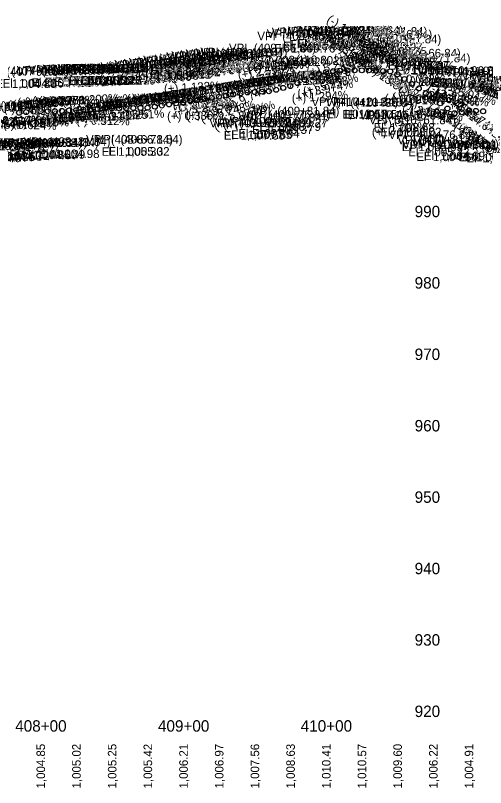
# Model space of a CAD drawing. Extents: x 16972137 to 16976737, y 12558490 to 12559551.
# Drawn here: x 16975172 to 16975501, y 12558490 to 12559031 of the extents above; entities that cross this region are included whole.
import ezdxf

# ---------------------------------------------------------------- set-up
doc = ezdxf.new("R2010")
doc.units = 0
for name, color, linetype in [('RD_DDB_ElevTX', 7, 'Continuous'), ('RD_DDB_GradeTX', 7, 'Continuous'), ('RD_DDB_PI', 7, 'Continuous'), ('RD_DDB_StaTX', 7, 'Continuous'), ('RD_DDB_StripGrade_PR', 7, 'Continuous')]:
    doc.layers.add(name, color=color, linetype=linetype)

msp = doc.modelspace()

# ---------------------------------------------------------------- linework, layer by layer
at = {"layer": 'RD_DDB_PI'}
for centre in [(16975399.74, 12558991.93), (16975404.74, 12558992.17), (16975409.74, 12558992.19), (16975414.74, 12558992.16), (16975419.74, 12558992.16), (16975424.74, 12558991.88), (16975379.74, 12558988.12), (16975384.74, 12558989.77), (16975389.74, 12558990.95), (16975394.74, 12558991.6), (16975429.74, 12558991.62), (16975434.74, 12558991.42), (16975439.74, 12558989.42), (16975364.74, 12558981.16), (16975369.74, 12558983.25), (16975374.74, 12558985.68), (16975444.74, 12558986.08), (16975449.74, 12558982.72), (16975329.74, 12558975.94), (16975334.74, 12558976.66), (16975339.74, 12558976.94), (16975344.74, 12558977.21), (16975349.74, 12558977.54), (16975354.74, 12558978.53), (16975359.74, 12558979.85), (16975454.74, 12558979.44), (16975459.74, 12558976.17), (16975294.74, 12558970.63), (16975299.74, 12558971.41), (16975304.74, 12558972.17), (16975309.74, 12558972.94), (16975314.74, 12558973.7), (16975319.74, 12558974.45), (16975324.74, 12558975.2), (16975464.74, 12558972.74), (16975224.74, 12558964.83), (16975229.74, 12558965.11), (16975234.74, 12558965.36), (16975239.74, 12558965.51), (16975244.74, 12558965.61), (16975249.74, 12558965.68), (16975254.74, 12558965.75), (16975259.74, 12558965.82), (16975264.74, 12558965.9), (16975269.74, 12558966.7), (16975274.74, 12558967.5), (16975279.74, 12558968.29), (16975284.74, 12558969.08), (16975289.74, 12558969.86), (16975469.74, 12558969.07), (16975474.74, 12558965.41), (16975174.74, 12558962.48), (16975179.74, 12558962.9), (16975184.74, 12558963.33), (16975189.74, 12558963.63), (16975194.74, 12558963.55), (16975199.74, 12558963.47), (16975204.74, 12558963.78), (16975209.74, 12558964.13), (16975214.74, 12558964.23), (16975219.74, 12558964.55), (16975479.74, 12558962.09), (16975484.74, 12558962.76), (16975489.74, 12558964.02), (16975494.74, 12558963.79), (16975499.74, 12558963.47)]:
    msp.add_circle(centre, 1.75, dxfattribs=at)

# ---------------------------------------------------------------- texts
at = {"layer": 'RD_DDB_ElevTX'}
for s, p in [('1010', (16975448.52, 12558989.31)), ('1000', (16975448.52, 12558939.31)), ('990', (16975451.82, 12558889.31)), ('980', (16975451.82, 12558839.31)), ('970', (16975451.82, 12558789.31)), ('960', (16975451.82, 12558739.31)), ('950', (16975451.82, 12558689.31)), ('940', (16975451.82, 12558639.31)), ('930', (16975451.82, 12558589.31)), ('920', (16975451.82, 12558539.31))]:
    msp.add_text(s, height=8, dxfattribs=at).set_placement(p)
at = {"layer": 'RD_DDB_GradeTX'}
for s, rotation, p in [('(-) 13.342%', 326.2932, (16975389.68, 12559026.42)), ('(-) 8.018%', 338.1532, (16975381.13, 12559016.15)), ('(-) 13.453%', 326.0724, (16975388.24, 12559013.24)), ('(-) 13.063%', 326.8491, (16975404.49, 12559015.84)), ('(-) 13.741%', 325.5091, (16975412.28, 12559012.42)), ('(-) 13.124%', 326.7268, (16975394.42, 12559008.25)), ('(+) 6.582%', 18.2168, (16975396.62, 12558996.84)), ('(+) 4.734%', 13.3166, (16975402.77, 12558997.12)), ('(+) 9.735%', 25.955, (16975390.76, 12558983.47)), ('(+) 9.749%', 25.9875, (16975396.34, 12558986.2)), ('(+) 2.593%', 7.3885, (16975407.67, 12558996.3)), ('(-) 14.642%', 323.7924, (16975410.07, 12559001.6)), ('(+) 1.334%', 3.8169, (16975414.67, 12558995.94)), ('(+) 1.334%', 3.8169, (16975334.86, 12558990.61)), ('(+) 0.965%', 2.763, (16975338.79, 12558991.99)), ('(+) 0.065%', 0.1852, (16975343.73, 12558994.98)), ('(+) 0.002%', 0.0061, (16975353.5, 12558995.15)), ('(-) 0.802%', 357.7037, (16975368.67, 12558997.07)), ('(+) 5.243%', 14.6898, (16975376.84, 12558987.43)), ('(+) 8.377%', 22.7269, (16975386.01, 12558980.31)), ('(-) 14.642%', 323.7924, (16975415.07, 12558997.94)), ('(+) 0.965%', 2.763, (16975418.69, 12558995.85)), ('(+) 0.065%', 0.1852, (16975423.73, 12558995.23)), ('(-) 0.118%', 359.6608, (16975432.06, 12558995.06)), ('(-) 1.123%', 356.7861, (16975441.65, 12558993.94)), ('(+) 2.593%', 7.3885, (16975328.37, 12558986.02)), ('(-) 13.305%', 326.3658, (16975417.98, 12558992.36)), ('(+) 3.089%', 8.7788, (16975312.88, 12558976.47)), ('(+) 3.071%', 8.7294, (16975319.7, 12558977.51)), ('(+) 6.582%', 18.2168, (16975320.88, 12558971.91)), ('(+) 3.053%', 8.6796, (16975322.37, 12558977.9)), ('(+) 4.734%', 13.3166, (16975325.05, 12558978.72)), ('(+) 3.035%', 8.6293, (16975327.37, 12558978.65)), ('(+) 3.017%', 8.5788, (16975334.71, 12558979.74)), ('(+) 2.999%', 8.5278, (16975338.2, 12558980.25)), ('(+) 2.973%', 8.4553, (16975342.97, 12558980.94)), ('(+) 2.844%', 8.0934, (16975348.13, 12558981.59)), ('(-) 0.118%', 359.6608, (16975351.99, 12558983.53)), ('(+) 1.133%', 3.2426, (16975356.25, 12558980.88)), ('(-) 1.123%', 356.7861, (16975361.11, 12558986.44)), ('(+) 1.105%', 3.1627, (16975361.73, 12558981.16)), ('(-) 1.036%', 357.0359, (16975364.83, 12558985.97)), ('(+) 5.253%', 14.7169, (16975374.66, 12558974.46)), ('(+) 0.002%', 0.0061, (16975433.5, 12558983.16)), ('(-) 0.802%', 357.7037, (16975448.13, 12558981.88)), ('(-) 8.018%', 338.1532, (16975455.02, 12558986.52)), ('(-) 8.555%', 336.8409, (16975479.91, 12558984.55)), ('(+) 1.133%', 3.2426, (16975276.39, 12558976.35)), ('(+) 3.185%', 9.0495, (16975289.25, 12558972.85)), ('(+) 3.165%', 8.9932, (16975294.38, 12558973.65)), ('(+) 3.141%', 8.9248, (16975301.13, 12558974.69)), ('(+) 3.124%', 8.8765, (16975304.27, 12558975.16)), ('(+) 3.106%', 8.8279, (16975309.51, 12558975.96)), ('(+) 9.749%', 25.9875, (16975319.68, 12558962.18)), ('(+) 3.974%', 11.2377, (16975370.36, 12558972.46)), ('(-) 1.036%', 357.0359, (16975444.72, 12558981.83)), ('(-) 13.342%', 326.2932, (16975455.39, 12558982.58)), ('(-) 13.453%', 326.0724, (16975460.46, 12558979.12)), ('(-) 8.686%', 336.5257, (16975485.61, 12558982.47)), ('(-) 8.686%', 336.5257, (16975490.61, 12558980.3)), ('(-) 9.687%', 334.1562, (16975497.12, 12558980.17)), ('(+) 3.053%', 8.6796, (16975243.34, 12558965.84)), ('(+) 3.035%', 8.6293, (16975248.33, 12558966.65)), ('(+) 3.017%', 8.5788, (16975255.66, 12558967.82)), ('(+) 2.999%', 8.5278, (16975259.14, 12558968.4)), ('(+) 2.973%', 8.4553, (16975263.9, 12558969.19)), ('(+) 2.844%', 8.0934, (16975268.97, 12558970.33)), ('(+) 5.253%', 14.7169, (16975294.4, 12558965.78)), ('(+) 1.294%', 3.7033, (16975365.93, 12558969.57)), ('(-) 2.789%', 352.0614, (16975439.96, 12558974.84)), ('(-) 2.614%', 352.5549, (16975456.32, 12558971.95)), ('(-) 2.765%', 352.1274, (16975459.83, 12558971.95)), ('(-) 3.431%', 350.2663, (16975466.36, 12558973.01)), ('(-) 5.047%', 345.8371, (16975471.76, 12558976.82)), ('(+) 1.251%', 3.5806, (16975156.63, 12558963.6)), ('(+) 1.139%', 3.2587, (16975161.8, 12558964.25)), ('(+) 1.105%', 3.1629, (16975166.86, 12558964.64)), ('(+) 1.006%', 2.8782, (16975170.44, 12558965.13)), ('(+) 0.580%', 1.6608, (16975173.56, 12558966.59)), ('(+) 0.436%', 1.248, (16975178.63, 12558967.17)), ('(+) 0.277%', 0.7939, (16975184.06, 12558967.77)), ('(+) 0.268%', 0.7682, (16975188.58, 12558967.86)), ('(+) 1.200%', 3.4347, (16975204.94, 12558967.55)), ('(+) 3.185%', 9.0495, (16975210.31, 12558960.28)), ('(-) 0.313%', 359.1029, (16975209.84, 12558966.32)), ('(+) 3.165%', 8.9932, (16975215.42, 12558961.15)), ('(+) 3.141%', 8.9248, (16975222.16, 12558962.29)), ('(+) 3.124%', 8.8765, (16975225.29, 12558962.83)), ('(+) 3.106%', 8.8279, (16975230.52, 12558963.7)), ('(+) 0.414%', 1.1859, (16975230.56, 12558967.56)), ('(+) 3.089%', 8.7788, (16975233.88, 12558964.27)), ('(+) 3.071%', 8.7294, (16975240.68, 12558965.37)), ('(+) 1.139%', 3.2587, (16975241.66, 12558968.8)), ('(+) 1.105%', 3.1629, (16975246.73, 12558969.05)), ('(+) 1.006%', 2.8782, (16975250.33, 12558969.15)), ('(+) 0.580%', 1.6608, (16975253.52, 12558968.91)), ('(+) 0.436%', 1.248, (16975258.61, 12558968.92)), ('(+) 0.277%', 0.7939, (16975264.05, 12558968.88)), ('(+) 0.268%', 0.7682, (16975268.58, 12558968.94)), ('(+) 0.259%', 0.7426, (16975273.46, 12558968.99)), ('(+) 1.105%', 3.1627, (16975282.52, 12558964.76)), ('(+) 1.294%', 3.7033, (16975286.11, 12558964.4)), ('(-) 0.891%', 357.4484, (16975430.71, 12558969.65)), ('(-) 1.299%', 356.2842, (16975435.72, 12558970.63)), ('(+) 1.406%', 4.0225, (16975145.57, 12558962.63)), ('(-) 0.557%', 358.4036, (16975153.87, 12558964.12)), ('(-) 1.411%', 355.9634, (16975163.97, 12558962.81)), ('(+) 3.222%', 9.152, (16975203.11, 12558959.01)), ('(+) 3.222%', 9.152, (16975283.94, 12558959.88)), ('(+) 3.974%', 11.2377, (16975291.99, 12558956.89)), ('(+) 5.243%', 14.6898, (16975302.66, 12558955.58)), ('(+) 8.377%', 22.7269, (16975312.61, 12558949.56)), ('(+) 9.735%', 25.955, (16975319.33, 12558948.7)), ('(-) 3.065%', 351.2879, (16975442.84, 12558963.15)), ('(-) 2.846%', 351.9003, (16975448.13, 12558961.68)), ('(-) 13.124%', 326.7268, (16975460.49, 12558964.9)), ('(-) 13.063%', 326.8491, (16975464.09, 12558962.58)), ('(-) 13.741%', 325.5091, (16975477.34, 12558967.72)), ('(-) 14.642%', 323.7924, (16975480.75, 12558964.74)), ('(+) 1.409%', 4.0302, (16975181.21, 12558953.8)), ('(+) 1.639%', 4.6854, (16975186, 12558954.37)), ('(+) 1.652%', 4.7219, (16975190.83, 12558954.78)), ('(+) 0.259%', 0.7426, (16975193.62, 12558955.96)), ('(+) 1.665%', 4.758, (16975196.18, 12558955.24)), ('(+) 0.336%', 0.9625, (16975198.43, 12558955.78)), ('(+) 1.719%', 4.9123, (16975203.15, 12558955.88)), ('(+) 1.223%', 3.4983, (16975220.14, 12558955.7)), ('(+) 1.406%', 4.0225, (16975226.21, 12558956.27)), ('(+) 1.251%', 3.5806, (16975237.21, 12558956.62)), ('(+) 0.336%', 0.9625, (16975278.41, 12558957.13)), ('(+) 5.018%', 14.0851, (16975426.48, 12558951.24)), ('(-) 0.545%', 358.4399, (16975138.37, 12558952.02)), ('(+) 1.223%', 3.4983, (16975140.29, 12558950.82)), ('(+) 0.425%', 1.2186, (16975143.69, 12558952.79)), ('(+) 0.414%', 1.1859, (16975150.83, 12558953.91)), ('(+) 0.617%', 1.766, (16975151.07, 12558953.15)), ('(-) 0.624%', 358.2125, (16975163.45, 12558951.57)), ('(+) 0.310%', 0.8881, (16975170.23, 12558952.32)), ('(+) 0.911%', 2.6078, (16975177.55, 12558953.11)), ('(-) 0.312%', 359.107, (16975214.72, 12558954.24)), ('(+) 2.701%', 7.6924, (16975422.23, 12558945.24)), ('(-) 14.642%', 323.7924, (16975478.66, 12558951.39)), ('(-) 13.305%', 326.3658, (16975483.75, 12558948.61))]:
    msp.add_text(s, height=6, rotation=rotation, dxfattribs=at).set_placement(p)
at = {"layer": 'RD_DDB_PI'}
for s, p in [('VPI  (409+91.84)', (16975348.27, 12559014.77)), ('VPI  (409+96.84)', (16975351.74, 12559015.95)), ('VPI  (410+01.84)', (16975359.69, 12559016.6)), ('VPI  (410+06.84)', (16975363.16, 12559016.93)), ('VPI  (410+11.84)', (16975371.35, 12559017.17)), ('VPI  (410+16.84)', (16975374.81, 12559017.19)), ('VPI  (410+26.84)', (16975382.92, 12559017.16)), ('VPI  (410+41.84)', (16975399.81, 12559016.42)), ('VPI  (410+46.84)', (16975403.27, 12559014.42)), ('VPI  (409+86.84)', (16975341.62, 12559013.12)), ('VPI  (410+51.84)', (16975409.57, 12559011.08)), ('VPI  (409+66.84)', (16975321.74, 12559004.85)), ('El  1,009.76', (16975353.46, 12559004.62)), ('El  1,010.09', (16975359.7, 12559006.27)), ('El  1,010.33', (16975364.02, 12559007.45)), ('El  1,010.46', (16975369.82, 12559008.1)), ('El  1,010.52', (16975374.26, 12559008.43)), ('El  1,010.57', (16975379.76, 12559008.67)), ('El  1,010.58', (16975384.5, 12559008.69)), ('El  1,010.57', (16975394.76, 12559008.66)), ('El  1,010.42', (16975409.5, 12559007.92)), ('El  1,010.02', (16975414.38, 12559005.92)), ('VPI  (409+21.84)', (16975277.92, 12558998.7)), ('VPI  (409+26.84)', (16975281.39, 12558999.45)), ('VPI  (409+31.84)', (16975287.86, 12559000.2)), ('VPI  (409+36.84)', (16975291.33, 12559000.94)), ('VPI  (409+41.84)', (16975298.27, 12559001.66)), ('VPI  (409+46.84)', (16975301.74, 12559001.94)), ('El  1,009.35', (16975417.66, 12559002.58)), ('VPI  (410+66.84)', (16975423.27, 12559001.17)), ('VPI  (408+86.84)', (16975241.5, 12558993.29)), ('VPI  (408+91.84)', (16975248.16, 12558994.08)), ('VPI  (408+96.84)', (16975251.62, 12558994.86)), ('VPI  (409+01.84)', (16975258.16, 12558995.63)), ('VPI  (409+06.84)', (16975261.62, 12558996.41)), ('VPI  (409+11.84)', (16975269.81, 12558997.17)), ('VPI  (409+16.84)', (16975273.27, 12558997.94)), ('El  1,007.47', (16975308.64, 12558993.16)), ('El  1,007.53', (16975312.84, 12558993.44)), ('El  1,008.11', (16975336.24, 12558996.35)), ('VPI  (410+71.84)', (16975429.99, 12558997.74)), ('El  1,007.37', (16975433.23, 12558992.67)), ('VPI  (407+91.84)', (16975148.45, 12558988.33)), ('VPI  (407+96.84)', (16975151.92, 12558988.63)), ('VPI  (408+16.84)', (16975173.16, 12558989.13)), ('VPI  (408+26.84)', (16975181.27, 12558989.55)), ('VPI  (408+31.84)', (16975187.74, 12558989.83)), ('VPI  (408+36.84)', (16975191.21, 12558990.11)), ('VPI  (408+41.84)', (16975198.16, 12558990.36)), ('VPI  (408+46.84)', (16975201.62, 12558990.51)), ('VPI  (408+51.84)', (16975207.92, 12558990.61)), ('VPI  (408+56.84)', (16975211.39, 12558990.68)), ('VPI  (408+61.84)', (16975218.16, 12558990.75)), ('VPI  (408+76.84)', (16975231.8, 12558991.7)), ('VPI  (408+81.84)', (16975238.04, 12558992.5)), ('El  1,006.42', (16975272.96, 12558987.91)), ('El  1,006.57', (16975278.23, 12558988.67)), ('El  1,006.73', (16975283.08, 12558989.44)), ('El  1,006.88', (16975288.08, 12558990.2)), ('El  1,007.03', (16975292.96, 12558990.95)), ('El  1,007.18', (16975299.91, 12558991.7)), ('El  1,007.33', (16975302.66, 12558992.44)), ('El  1,006.68', (16975438.2, 12558989.24)), ('VPI  (410+96.84)', (16975453.27, 12558989.02)), ('VPI  (411+01.84)', (16975461.35, 12558988.79)), ('VPI  (411+06.84)', (16975464.81, 12558988.47)), ('VPI  (411+11.84)', (16975473, 12558987.77)), ('El  1,005.21', (16975209.23, 12558981.86)), ('El  1,005.24', (16975212.69, 12558982.01)), ('El  1,005.26', (16975217.69, 12558982.11)), ('El  1,005.27', (16975222.87, 12558982.18)), ('El  1,005.29', (16975227.69, 12558982.25)), ('El  1,005.48', (16975242.96, 12558983.2)), ('El  1,005.64', (16975248.05, 12558984)), ('El  1,005.80', (16975252.81, 12558984.79)), ('El  1,005.95', (16975257.84, 12558985.58)), ('El  1,006.11', (16975266.36, 12558986.36)), ('El  1,006.26', (16975267.93, 12558987.13)), ('VPI  (411+26.84)', (16975484.57, 12558985.64)), ('VPI  (411+31.84)', (16975491.05, 12558984.95)), ('VPI  (411+36.84)', (16975494.51, 12558984.09)), ('El  1,004.80', (16975158.05, 12558979.83)), ('El  1,004.86', (16975163.17, 12558980.13)), ('El  1,004.96', (16975183.28, 12558980.63)), ('El  1,005.05', (16975192.72, 12558981.05)), ('El  1,005.10', (16975199.47, 12558981.33)), ('El  1,005.16', (16975204.58, 12558981.61)), ('El  1,004.94', (16975463.28, 12558980.52)), ('El  1,004.90', (16975468.17, 12558980.29)), ('El  1,004.83', (16975472.78, 12558979.97)), ('El  1,004.69', (16975478.28, 12558979.27)), ('El  1,004.27', (16975493.11, 12558977.14)), ('El  1,004.13', (16975499.44, 12558976.45)), ('VPI  (410+21.84)', (16975379.46, 12558967.16)), ('VPI  (410+31.84)', (16975389.4, 12558966.88)), ('VPI  (410+36.84)', (16975392.86, 12558966.62)), ('VPI  (409+81.84)', (16975338.16, 12558960.68)), ('VPI  (409+71.84)', (16975328.45, 12558956.16)), ('VPI  (409+76.84)', (16975331.92, 12558958.25)), ('El  1,010.57', (16975389.76, 12558958.66)), ('El  1,010.51', (16975401.12, 12558958.38)), ('El  1,010.46', (16975404.82, 12558958.12)), ('VPI  (410+56.84)', (16975413.04, 12558957.72)), ('VPI  (409+51.84)', (16975308.04, 12558952.21)), ('VPI  (409+56.84)', (16975311.5, 12558952.54)), ('VPI  (409+61.84)', (16975318.27, 12558953.53)), ('El  1,008.79', (16975343.34, 12558949.75)), ('El  1,009.27', (16975348.11, 12558952.18)), ('VPI  (410+61.84)', (16975419.81, 12558954.44)), ('El  1,007.65', (16975323.26, 12558944.04)), ('El  1,007.84', (16975328.34, 12558945.03)), ('El  1,008.37', (16975337.93, 12558947.66)), ('El  1,008.68', (16975423.08, 12558949.22)), ('El  1,008.02', (16975427.72, 12558945.94)), ('VPI  (410+76.84)', (16975433.45, 12558944.07)), ('VPI  (408+01.84)', (16975158.04, 12558938.55)), ('VPI  (408+11.84)', (16975169.69, 12558938.78)), ('VPI  (408+21.84)', (16975177.8, 12558939.23)), ('VPI  (408+66.84)', (16975221.62, 12558940.82)), ('VPI  (408+71.84)', (16975228.33, 12558940.9)), ('El  1,007.58', (16975318.14, 12558943.71)), ('VPI  (410+81.84)', (16975439.69, 12558940.41)), ('VPI  (407+61.84)', (16975118.45, 12558936.08)), ('VPI  (407+66.84)', (16975121.92, 12558936.31)), ('VPI  (407+71.84)', (16975128.63, 12558936.66)), ('VPI  (407+76.84)', (16975132.09, 12558937.07)), ('VPI  (407+81.84)', (16975138.33, 12558937.48)), ('VPI  (407+86.84)', (16975141.8, 12558937.9)), ('VPI  (408+06.84)', (16975161.5, 12558938.47)), ('VPI  (410+86.84)', (16975443.16, 12558937.09)), ('El  1,005.95', (16975442.84, 12558935.57)), ('VPI  (410+91.84)', (16975449.81, 12558937.76)), ('VPI  (411+16.84)', (16975476.46, 12558937.01)), ('VPI  (411+21.84)', (16975481.11, 12558936.3)), ('El  1,004.40', (16975133.17, 12558927.81)), ('El  1,004.47', (16975138.46, 12558928.16)), ('El  1,004.55', (16975142.84, 12558928.57)), ('El  1,004.63', (16975147.9, 12558928.98)), ('El  1,004.72', (16975153.14, 12558929.4)), ('El  1,004.85', (16975167.96, 12558930.05)), ('El  1,004.83', (16975172.78, 12558929.97)), ('El  1,004.89', (16975178.17, 12558930.28)), ('El  1,004.98', (16975188.2, 12558930.73)), ('El  1,005.30', (16975232.52, 12558932.32)), ('El  1,005.32', (16975237.31, 12558932.4)), ('El  1,005.22', (16975447.37, 12558931.91)), ('El  1,004.56', (16975453.05, 12558928.59)), ('El  1,004.69', (16975458.28, 12558929.26)), ('El  1,004.54', (16975483.05, 12558928.51)), ('El  1,004.40', (16975488.17, 12558927.8))]:
    msp.add_text(s, height=6, dxfattribs=at).set_placement(p)
at = {"layer": 'RD_DDB_StaTX'}
for s, p in [('408+00', (16975172, 12558529.06)), ('409+00', (16975272, 12558529.06)), ('410+00', (16975372, 12558529.06))]:
    msp.add_text(s, height=8, dxfattribs=at).set_placement(p)
at = {"layer": 'RD_DDB_StripGrade_PR'}
for s, p in [('1,004.85', (16975192.9, 12558489.31)), ('1,005.02', (16975217.9, 12558489.31)), ('1,005.25', (16975242.9, 12558489.31)), ('1,005.42', (16975267.9, 12558489.31)), ('1,006.21', (16975292.9, 12558489.31)), ('1,006.97', (16975317.9, 12558489.31)), ('1,007.56', (16975342.9, 12558489.31)), ('1,008.63', (16975367.9, 12558489.31)), ('1,010.41', (16975392.9, 12558489.31)), ('1,010.57', (16975417.9, 12558489.31)), ('1,009.60', (16975442.9, 12558489.31)), ('1,006.22', (16975467.9, 12558489.31)), ('1,004.91', (16975492.9, 12558489.31))]:
    msp.add_text(s, height=6, rotation=90, dxfattribs=at).set_placement(p)

doc.saveas('drawing.dxf')
